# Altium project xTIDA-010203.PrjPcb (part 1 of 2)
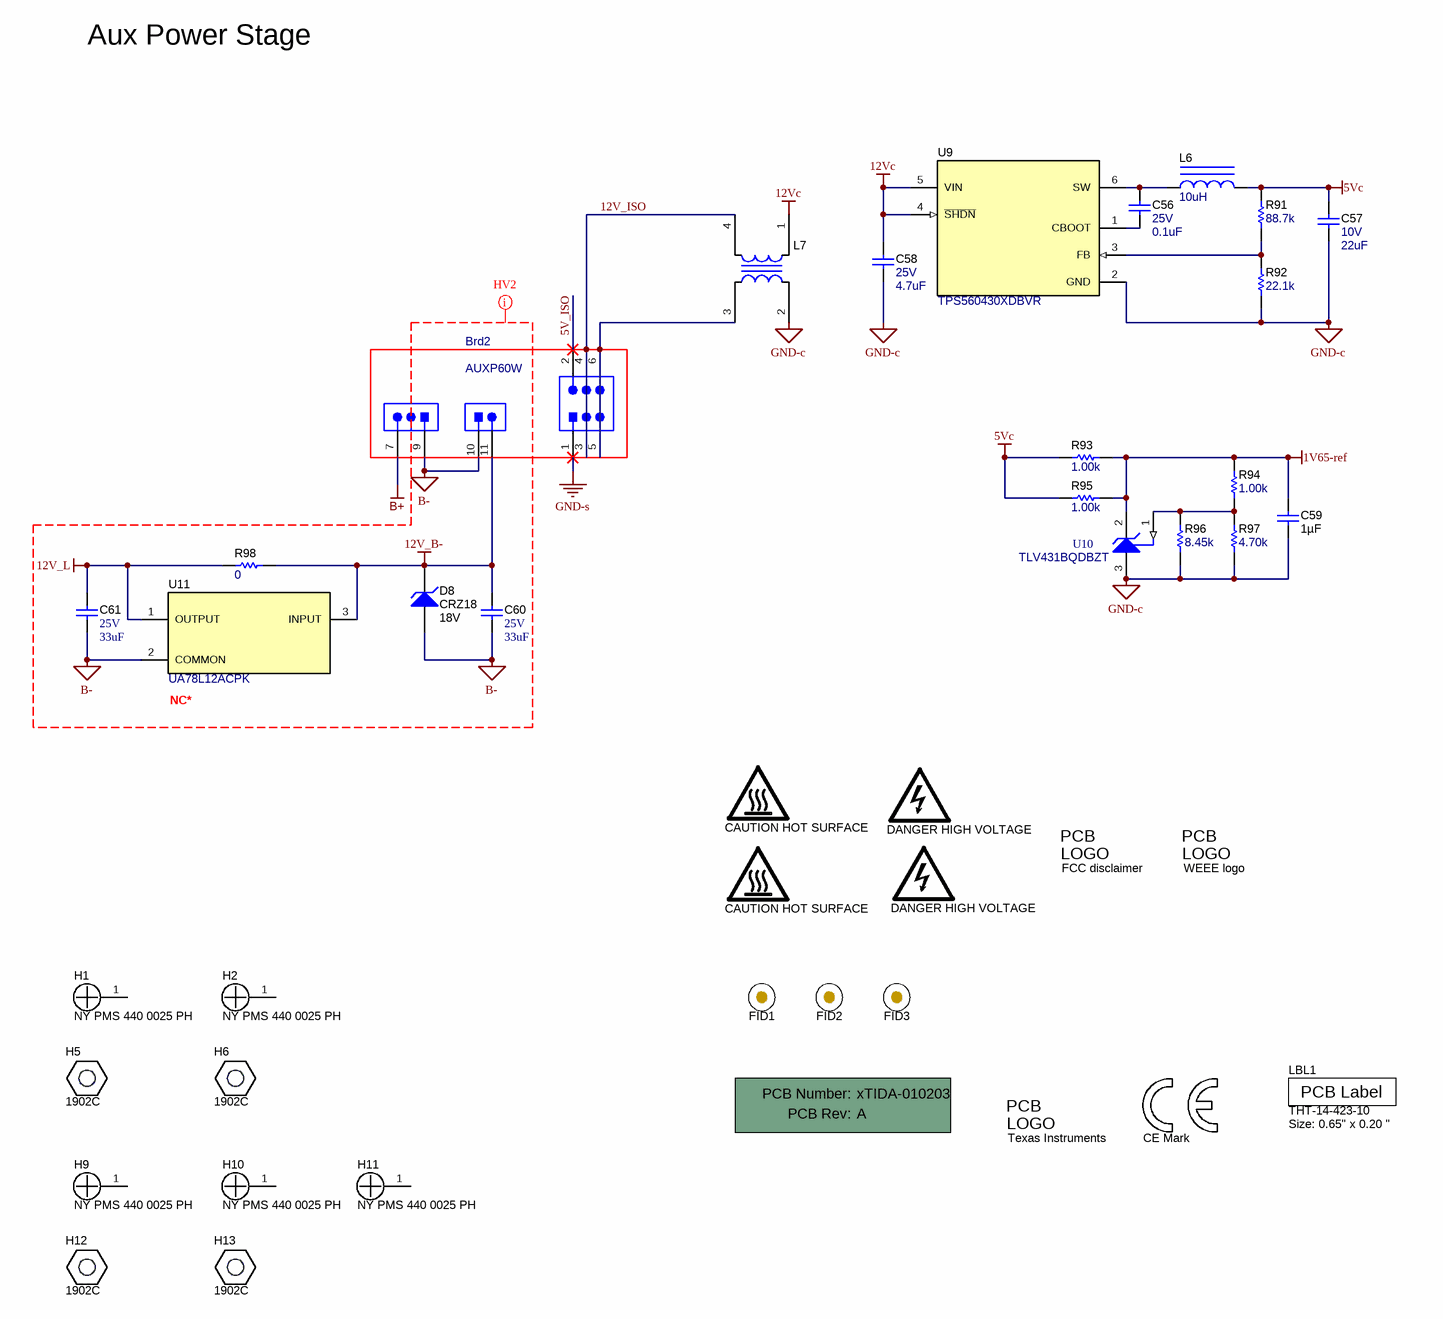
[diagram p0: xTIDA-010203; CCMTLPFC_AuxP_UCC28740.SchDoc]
CopyrightYear: 2020; EVM_orderable: Not Applicable; PCB_Layout: Desheng Guo; PCB_Rev: A; PRJ_Customer: Public Release; PRJ_Engineer: Desheng Guo; PRJ_Number: xTIDA-010203; PRJ_Title: Single Phase 4kW TPBL PFC; SCH_Rev: A; TechSupport: http://www.ti.com/support; TID: xTIDA-010203
4 sheets, 252 parts. Net scope: global (net labels, ports and power ports of the same name join across sheets).
Board file: xTIDA-010203_PCB.PcbDoc
Sheets:
  xTIDA-010203; CCMTLPFC_AuxP_UCC28740.SchDoc
  xTIDA-010203; CCMTLPFC_ControlStage.SchDoc
  xTIDA-010203; CCMTLPFC_PowerStage.SchDoc
  xTIDA-010203; Cover Page.SchDoc

## Sheet xTIDA-010203; CCMTLPFC_AuxP_UCC28740.SchDoc
size A3; Date: Not shown in title block; ApprovedBy: Not shown in title block; CheckedBy: Not shown in title block; Author: Not shown in title block; CompanyName: Not shown in title block; Engineer: Not shown in title block; Organization: Not shown in title block; Address1: Not shown in title block; Address2: Not shown in title block; Address3: Not shown in title block; Address4: Not shown in title block; DocumentNumber: 2; Revision: Use project parameter SCH_Rev; SheetNumber: 4; SheetTotal: 4; PageSetup: Record=PageOptions¦CenterHorizontal=True¦CenterVertical=True¦PrintScale=1.00¦XCorrection=1.00¦YCorrection=1.00¦PrintKind=0¦BorderSize=5000000¦LeftOffset=0¦BottomOffset=0¦Orientation=2¦PaperLength=1000¦PaperWidth=1000¦Scale=100¦PaperSource=15¦PrintQuality=600¦MediaType=1¦DitherType=10¦PaperKind=Letter¦PrintScaleMode=1

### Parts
!PCB1  Printed Circuit Board  (value not drawn)  (mechanical)
Brd2  AUXP60W  [AUXP60W]
C56  VDC_V: 25V  ValueDisplayed: 0.1uF  [0603]  (hidden comment: C1608X7R1E104K080AA)
C57  VDC_V: 10V  ValueDisplayed: 22uF  [0603]  (hidden comment: C1608X5R1A226M080AC)
C58  VDC_V: 25V  ValueDisplayed: 4.7uF  [0603]  (hidden comment: GRM188R61E475KE11D)
C59  ValueDisplayed: 1µF  [0603]  (hidden comment: GRM185R60J105KE26D)
C60  VDC_V: 25V  ValueDisplayed: 33uF  [1206_180]  (hidden comment: C3216X5R1E336M160AC)
C61  VDC_V: 25V  ValueDisplayed: 33uF  [1206_180]  (hidden comment: C3216X5R1E336M160AC)
D8  CRZ18  value 18V  [SOD-123]
FID1  Fiducial  [Fiducial10-20]  (value not drawn)  (no BOM)
FID2  Fiducial  [Fiducial10-20]  (value not drawn)  (no BOM)
FID3  Fiducial  [Fiducial10-20]  (value not drawn)  (no BOM)
H1  NY PMS 440 0025 PH  [NY PMS 440 0025 PH]  (no BOM)
H2  NY PMS 440 0025 PH  [NY PMS 440 0025 PH]  (no BOM)
H5  1902C  [Keystone_1902C]  (no BOM)
H6  1902C  [Keystone_1902C]  (no BOM)
H9  NY PMS 440 0025 PH  [NY PMS 440 0025 PH]  (no BOM)
H10  NY PMS 440 0025 PH  [NY PMS 440 0025 PH]  (no BOM)
H11  NY PMS 440 0025 PH  [NY PMS 440 0025 PH]  (no BOM)
H12  1902C  [Keystone_1902C]  (no BOM)
H13  1902C  [Keystone_1902C]  (no BOM)
L6  ValueDisplayed: 10uH  [VLS252010HBX]  (hidden comment: 74438323100)
L7  ACM2520-601-2P-T002  [TDK_ACM2520-2P]  (value not drawn)
LBL1  THT-14-423-10  Note: Size: 0.65" x 0.20 "  [Label_650x200]  (no BOM)
Logo1  Texas Instruments  [TI_Stacked_Overlay_Small]  (no BOM)
LOGO2  CAUTION HOT SURFACE  [IEC_HotSurface_Small]  (no BOM)
LOGO3  DANGER HIGH VOLTAGE  [IEC_HighVoltage_Small]  (no BOM)
LOGO4  CAUTION HOT SURFACE  [IEC_HotSurface_Small]  (no BOM)
LOGO5  DANGER HIGH VOLTAGE  [IEC_HighVoltage_Small]  (no BOM)
Logo6  FCC disclaimer  [FCC_disclaimer_stacked]  (no BOM)
Logo7  WEEE logo  [WEEE_Minimum]  (no BOM)
Logo8  CE Mark  [CE_Mark_5mm]  (no BOM)
R91  ValueDisplayed: 88.7k  [0603]  (hidden comment: CRCW060388K7FKEA)
R92  ValueDisplayed: 22.1k  [0603]  (hidden comment: CRCW060322K1FKEA)
R93  ValueDisplayed: 1.00k  [0603]  (hidden comment: ERJ-3EKF1001V)
R94  ValueDisplayed: 1.00k  [0603]  (hidden comment: ERJ-3EKF1001V)
R95  ValueDisplayed: 1.00k  [0603]  (hidden comment: ERJ-3EKF1001V)
R96  ValueDisplayed: 8.45k  [0603]  (hidden comment: RC0603FR-078K45L)
R97  ValueDisplayed: 4.70k  [0603]  (hidden comment: RC0603FR-074K7L)
R98  ValueDisplayed: 0  [0603]  (hidden comment: RC0603JR-070RL)
U9  TPS560430XDBVR  [DBV0006A_N]
U10  TLV431BQDBZT  [DBZ0003A_N]
U11  UA78L12ACPK  [PK0003A_M]  (no BOM)

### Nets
1V65-ref: C59.1 R93.2 R94.2 R95.2 U10.2(CATHODE)
5Vc: C57.1 L6.2 R91.2 R93.1 R95.1
12V_B-: Brd2.11(12Vp) C60.1 D8.1(K) R98.1 U11.3(INPUT)
12V_L: C61.1 R98.2 U11.1(OUTPUT)
12Vc: C58.1 L7.1 U9.4(~{SHDN}) U9.5(VIN)
B+: Brd2.7(B+)
B-: Brd2.9(B-) Brd2.10(GNDp) C60.2 C61.2 D8.2(A) U11.2(COMMON)
GND-c: C57.2 C58.2 C59.2 L7.2 R92.1 R96.1 R97.1 U9.2(GND) U10.3(ANODE)
GND-s: Brd2.1
5V_ISO: Brd2.2
12V_ISO: Brd2.3 Brd2.4 L7.4
NetBrd2_5: Brd2.5 Brd2.6 L7.3
NetC56_1: C56.1 L6.1 U9.6(SW)
NetC56_2: C56.2 U9.1(CBOOT)
NetR91_1: R91.1 R92.2 U9.3(FB)
NetR94_1: R94.1 R96.2 R97.2 U10.1(REF)

Not connected (* = marked no-connect by the designer): H1 1; H2 1; H9 1; H10 1; H11 1

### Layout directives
net class MV: 12V_B-, 12V_L, B+, B-

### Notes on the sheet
- Aux Power Stage
- (near U11) NC*

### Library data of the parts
!PCB1 = CMP-0003618-2: Manufacturer: Any; PartNumber: xTIDA-010203
Brd2 = AUXP60W: 60W AuxPower; Manufacturer: Texas Instrument; SymbolCreator: Use LDAP id; SymbolVersion: use current date i.e. 2008-05-20
C56 = CMP-0007039-5: CAP, CERM, 0.1 uF, 25 V, +/- 10%, X7R, 0603; Manufacturer: TDK; TaMin_C: -55°C; Polarized: N; SizeAreaWB_mm2: 4.68; Value1: Unknown; U/M: EA; Value: 0.1uF; TaMax_C: 125°C; SizeZ_mm: 1; SizeX_mm: 1.6; SizeY_mm: 0.8; SizeArea_mm2: 1.28; Cap_F: 100nF; AEC Category: Q200
C57 = CMP-0007005-1: CAP, CERM, 22 uF, 10 V, +/- 20%, X5R, 0603; Manufacturer: TDK; TaMin_C: -55°C; ESR_ohm: 3.71m; Polarized: N; SizeAreaWB_mm2: 4.68; Value1: 0.00371 ohm; U/M: EA; Value: 22uF; TaMax_C: 85°C; SizeZ_mm: 1; SizeX_mm: 1.6; SizeY_mm: 0.8; SizeArea_mm2: 1.28; Cap_F: 22µF; IRMS_A: 2.69936A; AEC Category: Q200
C58 = CMP-0007347-1: CAP, CERM, 4.7 uF, 25 V, +/- 10%, X5R, 0603; Manufacturer: MuRata; TaMin_C: -55°C; Polarized: N; SizeAreaWB_mm2: 4.68; Value1: Unknown; U/M: EA; Value: 4.7uF; TaMax_C: 85°C; SizeZ_mm: 1; SizeX_mm: 1.6; SizeY_mm: 0.8; SizeArea_mm2: 1.28; Cap_F: 4.7µF; AEC Category: Q200
C59 = GRM185R60J105KE26D: CAP, CERM, 1uF, 6.3V, +/-10%, X5R, 0603; Manufacturer: MuRata; Polarized: N; CompType: Capacitor; U/M: EA; Cap_F: 0.000001; Tolerance_%: 10; Value1: Unknown; VDC_V: 6.3; TaMin_C: -55; TaMax_C: 85
C60 C61 = CMP-0008655-2: CAP, CERM, 33 uF, 25 V, +/- 20%, X5R, 1206; Manufacturer: TDK; TaMin_C: -55°C; ESR_ohm: 2.648m; Polarized: N; SizeAreaWB_mm2: 10.92; Value1: 0.002648 ohm; U/M: EA; Value: 33uF; TaMax_C: 85°C; SizeZ_mm: 1.8; SizeX_mm: 3.2; SizeY_mm: 1.6; SizeArea_mm2: 5.12; Cap_F: 33µF; IRMS_A: 4.45864A; AEC Category: Q200
D8 = CMP-0005747-4: Diode, Zener, 18 V, 700 mW, SOD-123; Manufacturer: Toshiba; SizeAreaWB_mm2: 13.095; SizeArea_mm2: 6.545; SizeX_mm: 3.85; Value1: 0.7W; SizeY_mm: 1.7; Power_W: 700mW; SizeZ_mm: 1.35; RJA_CperW: 340; AEC Category: Q101
FID1-FID3 = CMP-0077181-1: Fiducial mark.  There is nothing to buy or mount.
H1 H2 H9-H11 = CMP-0003617-1: Machine Screw, Round, #4-40 x 1/4, Nylon, Philips panhead; Manufacturer: B&F Fastener Supply; CompType: Hardware
H5 H6 H12 H13 = CMP-0003610-1: Standoff, Hex, 0.5"L #4-40 Nylon; Manufacturer: Keystone; CompType: Hardware
L6 = CMP-0063086-1: Inductor, Wirewound, Ferrite, 10 uH, 0.68 A, 0.46 ohm, SMD; Manufacturer: Würth Elektronik; Isat: 1.35A @ 20% inductance drop; Irms: 0.60A @ 40C rise; Green_Lifecycle: Active; SizeAreaWB_mm2: 10.5; DCR_ohm: 0.46; Green_REACh: Passed; Value1: 0.843 ohm; Value: 10uH; Imax_A: 600mA; SizeZ_mm: 1; SizeX_mm: 2.5; SizeY_mm: 2; Value2: 0.6A; SizeArea_mm2: 5; Ind_H: 10µH; AEC Qualified: N; AEC Category: Q200
L7 = ACM2520-601-2P-T002: Coupled inductor, 0.2 A, 0.45 ohm, SMD; Manufacturer: TDK; SymbolCreator: a0799628; DCR_ohm: 0.45
LBL1 = CMP-0003625-1: Thermal Transfer Printable Labels, 0.650" W x 0.200" H - 10,000 per roll; Manufacturer: Brady; CompType: Label
Logo1 = CMP-0074838-1: Texas Instrument Corporate Signature; SymbolCreator: a0412235; Lib Reference: TI_Logo; Library Reference: Logo
LOGO2 LOGO4 = CMP-0074837-1: IEC 61010-1 Hot Surface Warning; SymbolCreator: a0412235; Lib Reference: IEC_HotSurface
LOGO3 LOGO5 = CMP-0074835-1: IEC 61010-1 High Voltage Warning; SymbolCreator: a0412235; Lib Reference: IEC_HighVoltage
Logo6 = CMP-0074847-1: FCC_disclaimer; Library Reference: Logo
Logo7 = CMP-0074769-1
Logo8 = CMP-0074844-1: SymbolCreator: a0412235
R91 = CMP-0022632-1: RES, 88.7 k, 1%, 0.1 W, 0603; Manufacturer: Vishay-Dale; Power_W: 100mW; TempCo: 100 ppm/C; Value_Code: 88k7; U/M: EA; Value: 88.7k; EIA_Code: E96; SizeX_mm: 1.6; SizeY_mm: 0.8; SizeZ_mm: 1; Value2: 0.1W; SizeArea_mm2: 1.28; VDC_V: 75V; AEC Category: Q200
R92 = CMP-0022220-1: RES, 22.1 k, 1%, 0.1 W, 0603; Manufacturer: Vishay-Dale; Power_W: 100mW; TempCo: 100 ppm/C; Value_Code: 22k1; U/M: EA; Value: 22.1k; EIA_Code: E96; SizeX_mm: 1.6; SizeY_mm: 0.8; SizeZ_mm: 1; Value2: 0.1W; SizeArea_mm2: 1.28; VDC_V: 75V; AEC Category: Q200
R93-R95 = CMP-0022680-4: RES, 1.00 k, 1%, 0.1 W, 0603; Manufacturer: Panasonic; Power_W: 100mW; TempCo: 100 ppm/C; Value_Code: 1k00; U/M: EA; Value: 1.00k; EIA_Code: E96; Res_ohm: 1k; SizeX_mm: 1.6; SizeY_mm: 0.8; SizeZ_mm: 1; SizeArea_mm2: 1.28; VDC_V: 75V; AEC Category: Q200; Value2: 0.1W
R96 = CMP-0023309-5: RES, 8.45 k, 1%, 0.1 W, 0603; Manufacturer: Yageo; Power_W: 100mW; TempCo: 100 ppm/C; Value_Code: 8k45; Value: 8.45k; EIA_Code: E96; SizeX_mm: 1.6; SizeY_mm: 0.8; SizeZ_mm: 1; Value2: 0.1W; SizeArea_mm2: 1.28; AEC Qualified: N; VDC_V: 75V; AEC Category: Q200; SizeAreaWB_mm2: 4.68
R97 = CMP-0023153-5: RES, 4.70 k, 1%, 0.1 W, 0603; Manufacturer: Yageo; Power_W: 100mW; TempCo: 100 ppm/C; Value_Code: 4k70; Value: 4.70k; Res_ohm: 4.7k; SizeX_mm: 1.6; SizeY_mm: 0.8; SizeZ_mm: 1; Value2: 0.1W; SizeArea_mm2: 1.28; AEC Qualified: N; VDC_V: 75V; AEC Category: Q200; SizeAreaWB_mm2: 4.68
R98 = CMP-0025885-5: RES, 0, 5%, 0.1 W, 0603; Manufacturer: Yageo; Power_W: 100mW; TempCo: 200 ppm/C; Value_Code: 0000; Value: 0; EIA_Code: E24; SizeX_mm: 1.6; SizeZ_mm: 1; Value2: 0.1W; SizeArea_mm2: 1.28; AEC Qualified: N; VDC_V: 75V; AEC Category: Q200; SizeY_mm: 0.8; SizeAreaWB_mm2: 4.68
U9 = CMP-0065097-1: 4V to 36 V 0.6 A Synchronous Step-Down Converter, DBV0006A (SOT-23-6); Alternate PartNumber: TPS560430XDBVT; Alternate Manufacturer: Texas Instruments; SizeAreaWB_mm2: 14.82; U/M: EA; SizeZ_mm: 1.45; SizeX_mm: 2.8; SizeY_mm: 2.9; SizeArea_mm2: 8.12; CompType: IC
U10 = CMP-0033012-1: Low-Voltage Adjustable Precision Shunt Regulator, 15 mA, -40 to 125 degC, 3-pin SOT-23 (DBZ), Green (RoHS & no Sb/Br); Manufacturer: Texas Instruments; Min Iz for Regulation(uA): 80; Iout/Iz(Max)(mA): 15; Temp Coeff(Max)(ppm/ degree C): 129; SubFamily: Shunt Voltage Reference; Rating: Catalog; VO Adj(Max)(V): 6; VO Adj(Min)(V): 1.24; Initial Accuracy @ 25/deg C(%): 0.5
U11 = CMP-0074738-2: 3 Pin 100mA Fixed 12V Positive Voltage Regulator, PK0003A (SOT-3); Manufacturer: Texas Instruments; SizeZ_mm: 1.6; SizeX_mm: 4.1; SizeY_mm: 4.5; SizeArea_mm2: 18.45; CompType: IC; U/M: EA; SizeAreaWB_mm2: 28.05

## Sheet xTIDA-010203; CCMTLPFC_ControlStage.SchDoc
size A3; Date: Not shown in title block; ApprovedBy: Not shown in title block; CheckedBy: Not shown in title block; Author: Not shown in title block; CompanyName: Not shown in title block; Engineer: Not shown in title block; Organization: Not shown in title block; Address1: Not shown in title block; Address2: Not shown in title block; Address3: Not shown in title block; Address4: Not shown in title block; DocumentNumber: 2; Revision: Use project parameter SCH_Rev; SheetNumber: 3; SheetTotal: 4; PageSetup: Record=PageOptions¦CenterHorizontal=True¦CenterVertical=True¦PrintScale=1.00¦XCorrection=1.00¦YCorrection=1.00¦PrintKind=0¦BorderSize=5000000¦LeftOffset=0¦BottomOffset=0¦Orientation=2¦PaperLength=1000¦PaperWidth=1000¦Scale=100¦PaperSource=15¦PrintQuality=600¦MediaType=1¦DitherType=10¦PaperKind=Letter¦PrintScaleMode=1
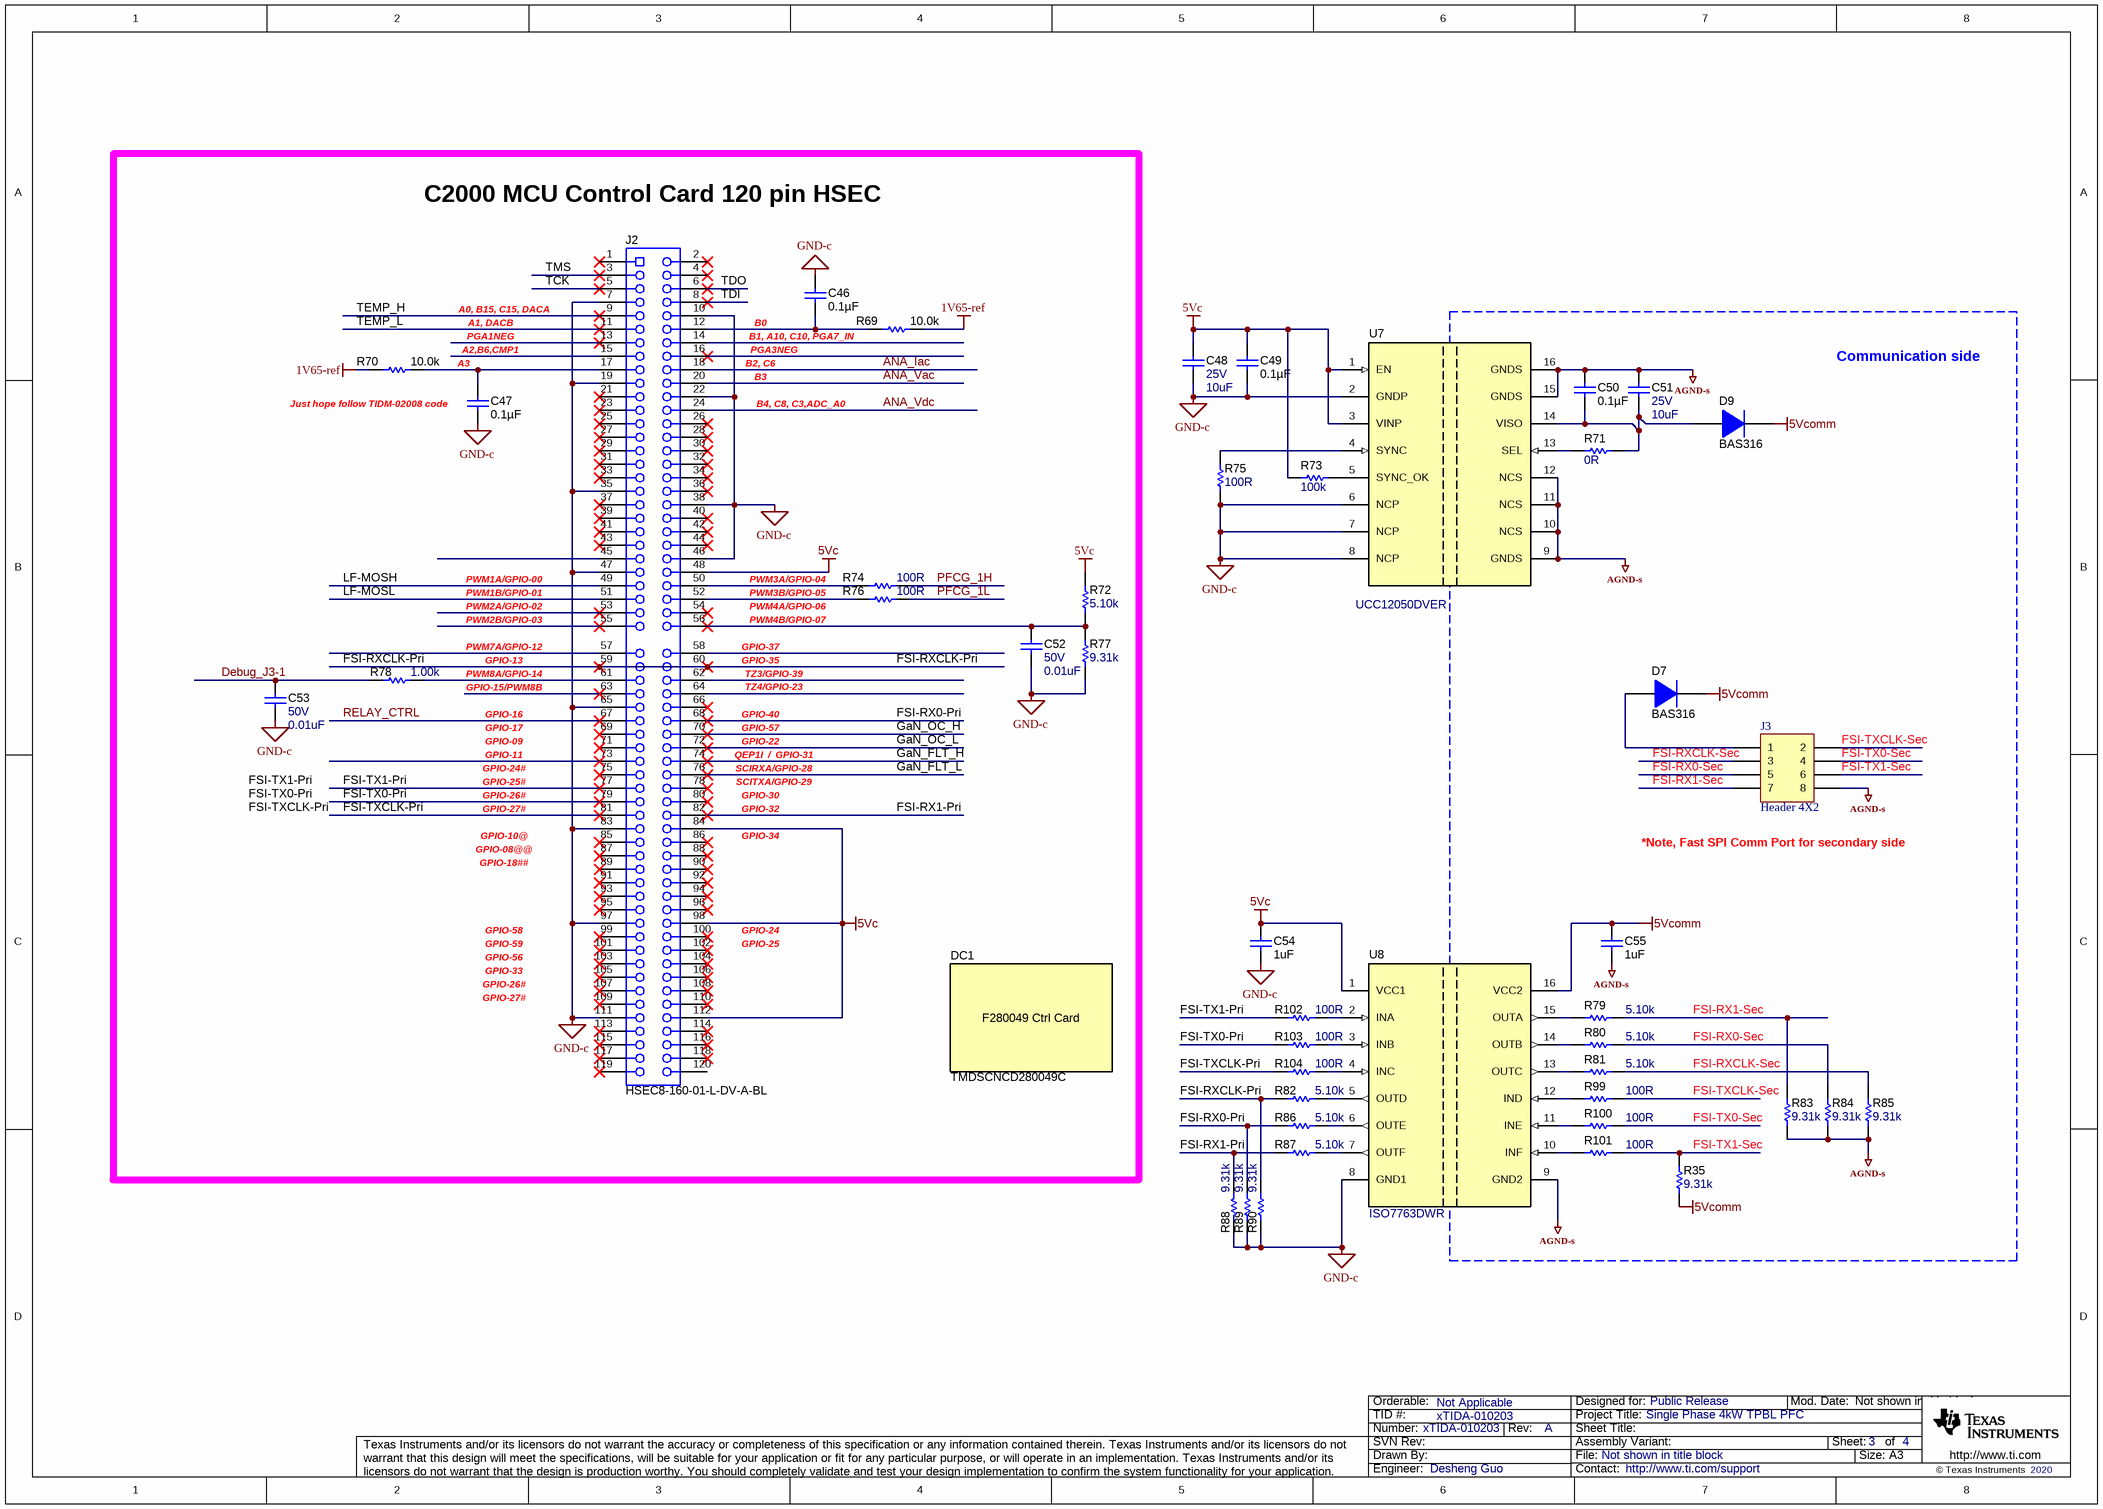
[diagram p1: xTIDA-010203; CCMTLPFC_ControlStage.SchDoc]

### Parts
C46  ValueDisplayed: 0.1µF  [0603]  (hidden comment: GRM188R71E104KA01D)
C47  ValueDisplayed: 0.1µF  [0603]  (hidden comment: GRM188R71E104KA01D)
C48  VDC_V: 25V  ValueDisplayed: 10uF  [0805_HV]  (hidden comment: GRM21BR61E106MA73L)
C49  ValueDisplayed: 0.1µF  [0603]  (hidden comment: GRM188R71E104KA01D)
C50  ValueDisplayed: 0.1µF  [0603]  (hidden comment: GRM188R71E104KA01D)
C51  VDC_V: 25V  ValueDisplayed: 10uF  [0805_HV]  (hidden comment: GRM21BR61E106MA73L)
C52  VDC_V: 50V  ValueDisplayed: 0.01uF  [0603]  (hidden comment: GRM188R71H103KA01D)
C53  VDC_V: 50V  ValueDisplayed: 0.01uF  [0603]  (hidden comment: GRM188R71H103KA01D)
C54  ValueDisplayed: 1uF  [0603]  (hidden comment: C1608X7R1E105K080AB)
C55  ValueDisplayed: 1uF  [0603]  (hidden comment: C1608X7R1E105K080AB)
D7  BAS316  [sod-323]
D9  BAS316  [sod-323]
DC1  TMDSCNCD280049C  (net tie)
J2  HSEC8-160-01-L-DV-A-BL  [controlCARD-120HSEC]
J3  Header 4X2  [HDR2X4]
R35  ValueDisplayed: 9.31k  [0603]  (hidden comment: RC0603FR-079K31L)
R69  ValueDisplayed: 10.0k  [0603]  (hidden comment: CRCW060310K0FKEA)
R70  ValueDisplayed: 10.0k  [0603]  (hidden comment: CRCW060310K0FKEA)
R71  ValueDisplayed: 0R  [0603]  (hidden comment: 0R 0603)
R72  ValueDisplayed: 5.10k  [0603]  (hidden comment: RC0603FR-075K1L)
R73  ValueDisplayed: 100k  [0603]  (hidden comment: 100k 0603)
R74  ValueDisplayed: 100R  [0603]  (hidden comment: 100R 0603)
R75  ValueDisplayed: 100R  [0603]  (hidden comment: 100R 0603)
R76  ValueDisplayed: 100R  [0603]  (hidden comment: 100R 0603)
R77  ValueDisplayed: 9.31k  [0603]  (hidden comment: RC0603FR-079K31L)
R78  ValueDisplayed: 1.00k  [0603]  (hidden comment: ERJ-3EKF1001V)
R79  ValueDisplayed: 5.10k  [0603]  (hidden comment: RC0603FR-075K1L)
R80  ValueDisplayed: 5.10k  [0603]  (hidden comment: RC0603FR-075K1L)
R81  ValueDisplayed: 5.10k  [0603]  (hidden comment: RC0603FR-075K1L)
R82  ValueDisplayed: 5.10k  [0603]  (hidden comment: RC0603FR-075K1L)
R83  ValueDisplayed: 9.31k  [0603]  (hidden comment: RC0603FR-079K31L)
R84  ValueDisplayed: 9.31k  [0603]  (hidden comment: RC0603FR-079K31L)
R85  ValueDisplayed: 9.31k  [0603]  (hidden comment: RC0603FR-079K31L)
R86  ValueDisplayed: 5.10k  [0603]  (hidden comment: RC0603FR-075K1L)
R87  ValueDisplayed: 5.10k  [0603]  (hidden comment: RC0603FR-075K1L)
R88  ValueDisplayed: 9.31k  [0603]  (hidden comment: RC0603FR-079K31L)
R89  ValueDisplayed: 9.31k  [0603]  (hidden comment: RC0603FR-079K31L)
R90  ValueDisplayed: 9.31k  [0603]  (hidden comment: RC0603FR-079K31L)
R99  ValueDisplayed: 100R  [0603]  (hidden comment: 100R 0603)
R100  ValueDisplayed: 100R  [0603]  (hidden comment: 100R 0603)
R101  ValueDisplayed: 100R  [0603]  (hidden comment: 100R 0603)
R102  ValueDisplayed: 100R  [0603]  (hidden comment: 100R 0603)
R103  ValueDisplayed: 100R  [0603]  (hidden comment: 100R 0603)
R104  ValueDisplayed: 100R  [0603]  (hidden comment: 100R 0603)
U7  UCC12050DVER  [DVE0016A]
U8  ISO7763DWR  [DW0016B_HV]

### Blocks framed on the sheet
C2000 MCU Control Card 120 pin HSEC: C46 C47 C52 C53 DC1 J2 R69 R70 R72 R74 R76-R78
Communication side: C50 C51 C55 D7 D9 J3 R35 R71 R79-R81 R83-R85 R99-R101 U7 U8

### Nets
1V65-ref: R69.2 R70.1
5Vc: C48.1 C49.2 C54.2 J2.48 J2.84 J2.98 J2.112 R72.2 R73.2 U7.1(EN) U7.3(VINP) U8.1(VCC1)
5Vcomm: C55.2 D7.1(K) D9.1(K) R35.1 U8.16(VCC2)
AGND-s: C50.2 C51.1 C55.1 J3.8 R83.1 R84.1 R85.1 U7.9(GNDS) U7.10(NCS) U7.11(NCS) U7.12(NCS) U7.15(GNDS) U7.16(GNDS) U8.9(GND2)
GND-c: C46.1 C47.1 C48.2 C49.1 C52.2 C53.2 C54.1 J2.7 J2.10 J2.19 J2.22 J2.35 J2.38 J2.46 J2.47 J2.65 J2.83 J2.97 J2.111 R75.1 R77.1 R88.1 R89.1 R90.1 U7.2(GNDP) U7.6(NCP) U7.7(NCP) U7.8(NCP) U8.8(GND1)
ANA_Iac: J2.18
ANA_Vac: J2.20
ANA_Vdc: J2.24
Debug_J3-1: C53.1 R78.1
FSI-RX0-Pri: J2.68 R86.2 R89.2
FSI-RX0-Sec: J3.5 R80.1 R84.2
FSI-RX1-Pri: J2.82 R87.2 R88.2
FSI-RX1-Sec: J3.7 R79.1 R83.2
FSI-RXCLK-Pri: J2.59 J2.60 R82.2 R90.2
FSI-RXCLK-Sec: J3.3 R81.1 R85.2
FSI-TX0-Pri: J2.79 R103.2
FSI-TX0-Sec: J3.4 R100.1
FSI-TX1-Pri: J2.77 R102.2
FSI-TX1-Sec: J3.6 R35.2 R101.1
FSI-TXCLK-Pri: J2.81 R104.2
FSI-TXCLK-Sec: J3.2 R99.1
GaN_FLT_H: J2.74
GaN_FLT_L: J2.76
GaN_OC_H: J2.70
GaN_OC_L: J2.72
LF-MOSH: J2.49
LF-MOSL: J2.51
PFCG_1H: R74.1
PFCG_1L: R76.1
RELAY_CTRL: J2.67
TCK: J2.5
TDI: J2.8
TDO: J2.6
TEMP_H: J2.9
TEMP_L: J2.11
TMS: J2.3
NetC46_2: C46.2 J2.12 R69.1
NetC47_2: C47.2 J2.17 R70.2
NetC50_1: C50.1 C51.2 D9.2(A) R71.1 U7.14(VISO)
NetC52_1: C52.1 J2.56 R72.1 R77.2
NetD7_2: D7.2(A) J3.1
NetJ2_50: J2.50 R74.2
NetJ2_52: J2.52 R76.2
NetJ2_61: J2.61 R78.2
NetR71_2: R71.2 U7.13(SEL)
NetR73_1: R73.1 U7.5(SYNC_OK)
NetR75_2: R75.2 U7.4(SYNC)
NetR79_2: R79.2 U8.15(OUTA)
NetR80_2: R80.2 U8.14(OUTB)
NetR81_2: R81.2 U8.13(OUTC)
NetR82_1: R82.1 U8.5(OUTD)
NetR86_1: R86.1 U8.6(OUTE)
NetR87_1: R87.1 U8.7(OUTF)
NetR99_2: R99.2 U8.12(IND)
NetR100_2: R100.2 U8.11(INE)
NetR101_2: R101.2 U8.10(INF)
NetR102_1: R102.1 U8.2(INA)
NetR103_1: R103.1 U8.3(INB)
NetR104_1: R104.1 U8.4(INC)

Not connected (* = marked no-connect by the designer): J2 1* 2* 4* 13* 14 15 16* 21* 23* 25* 26* 27* 28* 29* 30* 31* 32* 33* 34* 36* 37* 39* 40* 41* 42* 43* 44* 45 53* 54* 55* 57 58 62 63* 64 66* 69* 71* 73* 75* 78* 80* 85* 86* 87* 88* 89* 90* 91* 92* 93* 94* 95* 96* 99* 100* 101* 102* 103* 104* 105* 106* 107* 108* 109* 110* 113* 114* 115* 116* 117* 118* 119* 120

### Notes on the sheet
- A1, DACB
- A0, B15, C15, DACA
- B0
- A3
- PGA1NEG
- A2,B6,CMP1
- B2, C6
- B3
- (near C46) PGA3NEG
- B1, A10, C10, PGA7_IN
- Just hope follow TIDM-02008 code
- B4, C8, C3,ADC_A0
- PWM1A/GPIO-00
- PWM1B/GPIO-01
- PWM3A/GPIO-04
- PWM3B/GPIO-05
- PWM2A/GPIO-02
- PWM2B/GPIO-03
- PWM7A/GPIO-12
- GPIO-13
- GPIO-37
- GPIO-35
- PWM4A/GPIO-06
- PWM4B/GPIO-07
- PWM8A/GPIO-14
- GPIO-15/PWM8B
- GPIO-16
- GPIO-17
- GPIO-40
- GPIO-57
- TZ3/GPIO-39
- TZ4/GPIO-23
- GPIO-09
- GPIO-11
- GPIO-24#
- GPIO-25#
- GPIO-26#
- GPIO-22
- GPIO-30
- (near J2) QEP1I  /  GPIO-31
- SCIRXA/GPIO-28
- SCITXA/GPIO-29
- GPIO-27#
- GPIO-10@
- GPIO-08@@
- GPIO-18##
- GPIO-32
- GPIO-34
- (near J3) *Note, Fast SPI Comm Port for secondary side
- GPIO-58
- GPIO-24
- GPIO-59
- GPIO-56
- GPIO-33
- GPIO-25
- Labels drawn without touching a wire or pin: FSI-TX0-Pri, FSI-TX1-Pri, FSI-TXCLK-Pri

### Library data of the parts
C46 C47 C49 C50 = GRM188R71E104KA01D: CAP, CERM, 0.1 µF, 25 V,+/- 10%, X7R, 0603; Manufacturer: MuRata; Polarized: N; CompType: Capacitor; Value: 0.1uF; U/M: EA; Cap_F: 0.0000001; Tolerance_%: 10; VDC_V: 25; Value2: 25V; TaMin_C: -55; TaMax_C: 125; SizeArea_mm2: 1.28; SizeAreaWB_mm2: 4.68; SizeX_mm: 1.6; SizeY_mm: 0.8; SizeZ_mm: 1; AEC Category: Q200; Green_Lifecycle: Active; Green_REACh: Passed
C48 C51 = CMP-0008378-2: CAP, CERM, 10 uF, 25 V, +/- 10%, X5R, 0805; Manufacturer: MuRata; TaMin_C: -55°C; Polarized: N; SizeAreaWB_mm2: 6.75; Value1: Unknown; U/M: EA; Value: 10uF; TaMax_C: 85°C; SizeZ_mm: 1.45; SizeX_mm: 2; SizeY_mm: 1.25; Cap_Case: 0805; SizeArea_mm2: 2.5; Cap_F: 10µF; AEC Category: Q200
C52 C53 = CMP-0007433-4: CAP, CERM, 0.01 uF, 50 V, +/- 10%, X7R, 0603; Manufacturer: MuRata; TaMin_C: -55°C; Polarized: N; SizeAreaWB_mm2: 4.68; Value1: Unknown; U/M: EA; Value: 0.01uF; TaMax_C: 125°C; SizeZ_mm: 1; SizeX_mm: 1.6; SizeY_mm: 0.8; SizeArea_mm2: 1.28; Cap_F: 10nF; AEC Category: Q200
C54 C55 = C1608X7R1E105K080AB: CAP, CERM, 1uF, 25V, +/-10%, X7R, 0603; Manufacturer: TDK; Polarized: N; CompType: Capacitor; U/M: EA; Cap_F: 0.000001; Tolerance_%: 10; Value1: Unknown; VDC_V: 25; TaMin_C: -55; TaMax_C: 125
D7 D9 = BAS316,115: Diode, Ultrafast, 100 V, 0.25 A, SOD-323; Manufacturer: Toshiba; U/M: EA; Vf_V: 1.4; Value: 100V; Value1: 0.25A; Value2: 1.4V; Io_A: 0.25; Vr_V: 100; TJmax_C: 150
DC1 = TMDSCNCD280049C: F280049C control card; Manufacturer: Texas Instruments
J2 = controlCARD-120HSEC: C2000 controlCARD-120HSEC connector, SMT; Manufacturer: Samtec; SymbolCreator: a0412235; Note: The pin numbering does not match Samtec datasheet
J3 = Header 4X2: Header, 4-Pin, Dual row,2.54mm; Manufacturer: Any
R35 R77 R83-R85 R88-R90 = CMP-0023334-5: RES, 9.31 k, 1%, 0.1 W, 0603; Manufacturer: Yageo; Power_W: 100mW; TempCo: 100 ppm/C; Value_Code: 9k31; Value: 9.31k; EIA_Code: E96; SizeX_mm: 1.6; SizeY_mm: 0.8; SizeZ_mm: 1; Value2: 0.1W; SizeArea_mm2: 1.28; AEC Qualified: N; VDC_V: 75V; AEC Category: Q200; SizeAreaWB_mm2: 4.68
R69 R70 = CRCW060310K0FKEA: RES, 10.0 k, 1%, 0.1 W, 0603; Manufacturer: Vishay-Dale; Power_W: 0.1; TempCo: 100 ppm/C; Value_Code: 10k0; U/M: EA; Value: 10.0k; EIA_Code: E96; Tolerance_%: 1; Res_ohm: 10000; SizeX_mm: 1.6; SizeY_mm: 0.8; SizeArea_mm2: 1.28; CompType: Resistor; VDC_V: 75; AEC Category: Q200; Value2: 0.1W; Green_Lifecycle: Active; Green_REACh: Passed
R71 = CMP-0023198-5: RES, 0, 1%, 0.1 W, 0603; Manufacturer: Yageo; Power_W: 100mW; TempCo: 100 ppm/C; Value_Code: 0; Value: 0; SizeX_mm: 1.6; SizeY_mm: 0.8; SizeZ_mm: 1; Value2: 0.1W; SizeArea_mm2: 1.28; AEC Qualified: N; VDC_V: 75V; AEC Category: Q200; SizeAreaWB_mm2: 4.68
R72 R79-R82 R86 R87 = CMP-0023198-5: RES, 5.10 k, 1%, 0.1 W, 0603; Manufacturer: Yageo; Power_W: 100mW; TempCo: 100 ppm/C; Value_Code: 5k10; Value: 5.10k; Res_ohm: 5.1k; SizeX_mm: 1.6; SizeY_mm: 0.8; SizeZ_mm: 1; Value2: 0.1W; SizeArea_mm2: 1.28; AEC Qualified: N; VDC_V: 75V; AEC Category: Q200; SizeAreaWB_mm2: 4.68
R73 = CMP-0023198-5: RES, 100 k, 1%, 0.1 W, 0603; Manufacturer: Yageo; Power_W: 100mW; TempCo: 100 ppm/C; SizeX_mm: 1.6; SizeY_mm: 0.8; SizeZ_mm: 1; Value2: 0.1W; SizeArea_mm2: 1.28; AEC Qualified: N; VDC_V: 75V; AEC Category: Q200; SizeAreaWB_mm2: 4.68
R74-R76 R99-R104 = CMP-0023198-5: RES, 100R, 1%, 0.1 W, 0603; Manufacturer: Yageo; Power_W: 100mW; TempCo: 100 ppm/C; SizeX_mm: 1.6; SizeY_mm: 0.8; SizeZ_mm: 1; Value2: 0.1W; SizeArea_mm2: 1.28; AEC Qualified: N; VDC_V: 75V; AEC Category: Q200; SizeAreaWB_mm2: 4.68
R78 = CMP-0022680-4: as R93 on sheet xTIDA-010203; CCMTLPFC_AuxP_UCC28740
U7 = CMP-0081958-3: 500 mW, High-Efficiency, Low-Emissions, 5 kVRMS Isolated DC-DC Converter, DVE0016A (SO-MOD-16); Manufacturer: Texas Instruments; AEC Category: Q200; CompType: IC; SizeAreaWB_mm2: 151.29; SizeZ_mm: 2.65; AEC Qualified: N; SizeArea_mm2: 106.09; SizeY_mm: 10.3
U8 = CMP-0078433-2: High Speed, Robust EMC, Reinforced Six-Channel Digital Isolator, DW0016B (SOIC-16); Alternate Manufacturer: Texas Instruments; CompType: IC; SizeAreaWB_mm2: 152.52; SizeX_mm: 10.4; AEC Category: Q200; SizeZ_mm: 2.65; SizeArea_mm2: 107.12; AEC Qualified: N; SizeY_mm: 10.3; Rating: Catalog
